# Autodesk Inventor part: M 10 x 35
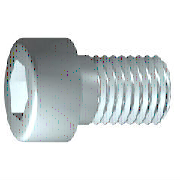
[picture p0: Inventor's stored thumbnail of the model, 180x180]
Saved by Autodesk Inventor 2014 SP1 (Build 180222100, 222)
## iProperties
IsCustomPart: 0
Created: 2009-02
Part Number: M 10 x 35
Material: 강, 연강
Description: 6각머리 태핑 나사
Document SubType Name: Modeling
Standard: KS B 1003
Designer: KYOUNG IL JANG
Standards Organization: KS
Language: ko-KR
Size Designation: M 10 x 35
Categories: <MemberInstance><Categories><Category DisplayName="조임쇠" InternalName="e4da775c-781d-43d5-af7c-5136215cf5a6" Mnemonic="FSTN"><Category DisplayName="볼트" InternalN
Density: 1 g/cm^3
Appearance: 강철
Author: KYOUNG IL JANG
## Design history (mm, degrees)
sketch "스케치1"
  geometry: L1 (-2.333, 0)-(35, 0); L2 (35, 0)-(35, 5); L3 (35, 5)-(3.75, 5); L4 (3.75, 5)-(2.83, 5); L5 (2.83, 5)-(0, 5); L6 (0, 5)-(0, 8); L7 (0, 8)-(-10, 8); L8 (-10, 8)-(-10, 4.619); L9 (-10, 4.619)-(-5, 4.619); L10 (-5, 4.619)-(-2.333, 0); L11 (-19, 0)-(44, 0) reference; L12 (0, -1.6)-(0, 9.6) reference; L13 (3.75, 5)-(0, 5)
  constraints: 22 end point, 6 parallel, 2 collinear, 2 perpendicular, 1 horizontal, 1 point on line
  dimensions: "d1" = 31.25 distance from line of L3.end L2 (= GEL); "d2" = 0.92028 distance of L4.end L3.end (computed from GAL); "d3" = 10 distance between parallel lines of L8 L6 (= KOH); "d4" = 5 distance of L8.end L9.end (= INTI); "d5" = 60 deg angle of L10 L1; "d6" = 10 diameter of L3 L1 (= GD); "d7" = 10 diameter of L5 L1 (= BDM); "d8" = 9.2376 diameter of L9 L1 (= 1.1547 x SW); "d9" = 16 diameter of L7 L1 (= KOD); "d26" = 35 distance between parallel lines of L12 L2 (= NLG)
revolve "본체" sketch "스케치1" stored, may be unused: angle "d10" = 90 deg
sketch "스케치2"
  geometry: L1 (0, -11.2)-(0, 11.2) reference; L2 (-11.2, 0)-(11.2, 0) reference; L3 (4.619, 0)-(2.309, -4); L4 (2.309, -4)-(-2.309, -4); L5 (-2.309, -4)-(-4.619, 0); L6 (-4.619, 0)-(-2.309, 4); L7 (-2.309, 4)-(2.309, 4); L8 (2.309, 4)-(4.619, 0); 2 further points
  constraints: 12 end point, 1 coincident, 1 horizontal alignment, 1 point on line, 12 other
extrude "슬롯" join sketch "스케치2" stored distance "d11" = 10; taper "d12" = 0 deg
workplane "Work Plane1"
fillet "Fillet2" dims "d30" = 0.1 (= R)
body "Solid1"
fillet "모깎기1" dims "d17" = 1 (= RR)
feature "스레드" dims "d13" = 31.25 (= GEL), "d14" = 0
chamfer "모따기1" distance "d15" = 0.92018 (= -0.5 x SPD + 0.5 x GD); stored, may be unused: second distance "d16" = 0.92018 (= GUL), angle "d27" = 45 deg
other parameters: "GD" = 10 (= NND) [user parameter; used in 2 equation terms], "NLG" = 35 [user parameter; used in 1 equation term], "GEL" = 31.25 [user parameter; used in 2 equation terms], "KOD" = 16 [user parameter; used in 1 equation term], "KOH" = 10 [user parameter; used in 1 equation term], "INTI" = 5 [user parameter; used in 1 equation term], "GAL" = 0.92018 (= 0.61345 x PTC) [user parameter; used in 1 equation term], "GUL" = 0.92018 (= 0.61345 x PTC) [user parameter; used in 1 equation term], "BDM" = 10 (= NND) [user parameter; used in 1 equation term], "SW" = 8 [user parameter; used in 2 equation terms], "RR" = 1 [user parameter; used in 1 equation term], "SPD" = 8.15965 (= NND - 1.2269 x PTC) [user parameter; used in 1 equation term], "d19" = 0, "d28" = 0, "d29" = 0, "R" = 0.1 [user parameter; used in 1 equation term], "PHH" = 0.4 [user parameter], "GD1" = 8.15965 (= THREADDIA - 1.2269 x PTC) [user parameter], "FAWI" = 45 deg [user parameter], "TPU" = 6.66667 (computed from PTC) [user parameter], "PTC" = 1.5 [user parameter; used in 5 equation terms], "TOA" = 30 deg [user parameter], "E0" = 9.24 (= 1.155 x SW) [user parameter]
